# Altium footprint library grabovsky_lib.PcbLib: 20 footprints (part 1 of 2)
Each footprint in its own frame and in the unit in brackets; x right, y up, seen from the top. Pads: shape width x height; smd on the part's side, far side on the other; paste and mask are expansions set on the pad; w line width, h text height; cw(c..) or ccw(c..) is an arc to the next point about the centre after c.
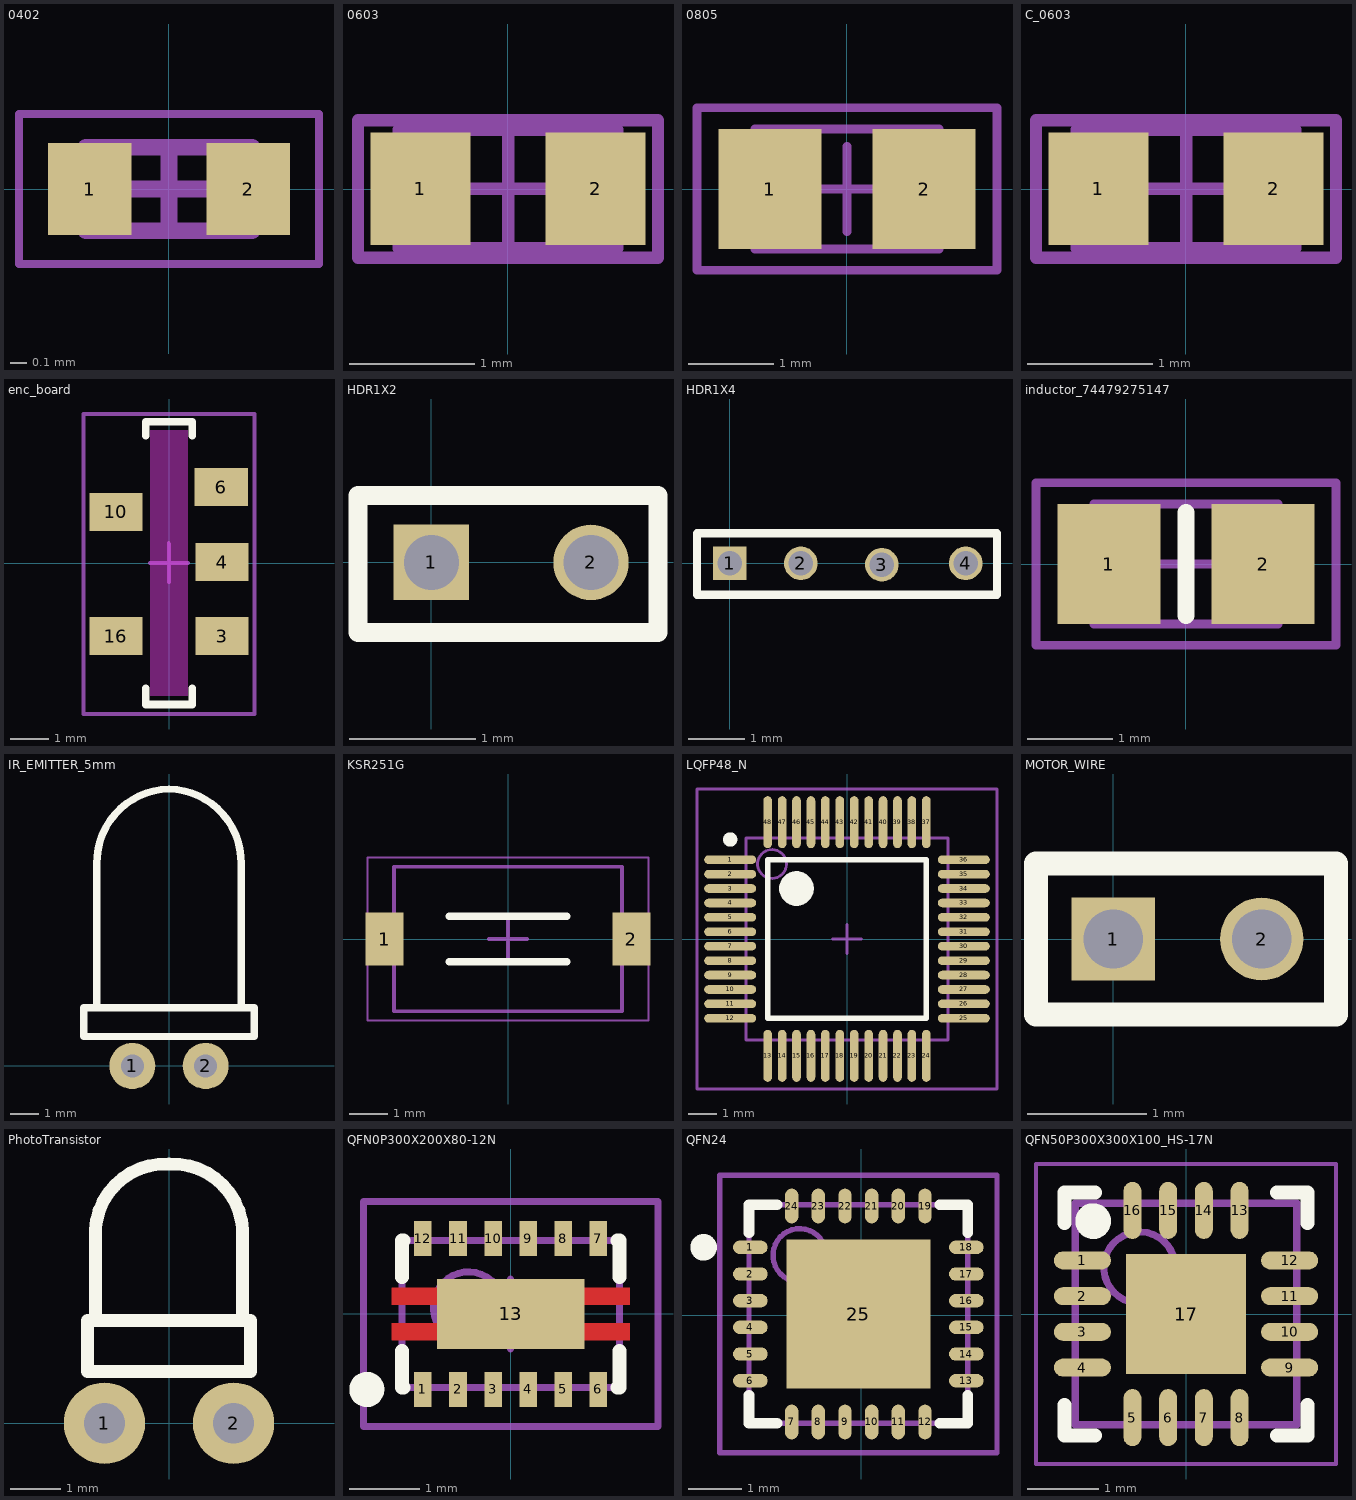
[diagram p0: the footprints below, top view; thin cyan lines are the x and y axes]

## 0402 [mm]
height 2
pads (2):
  rect 0.5x0.55 smd: 1(-0.475,0) 2(0.475,0)
Mechanical 13:
  lines w0.1: -0.5,-0.25 -0.5,0.25 0.5,0.25 0.5,-0.25 -0.5,-0.25
Mechanical 15:
  lines w0.05: -0.9,-0.45 -0.9,0.45 0.9,0.45 0.9,-0.45 -0.9,-0.45
  lines w0.1: -0.25,0 0.25,0 ; 0,-0.25 0,0.25
3D body "RES0402.stp": height 0.3, standoff 0, extent -0.5,-0.25 0.5,0.25

## 0603 [mm]
pads (2):
  rect 0.8x0.9 smd: 1(-0.7,0) 2(0.7,0)
Mechanical 13:
  lines w0.1: -0.875,-0.475 0.875,-0.475 0.875,0.475 -0.875,0.475 -0.875,-0.475
Mechanical 15:
  lines w0.1: -0.475,0 0.475,0 ; 0,-0.475 0,0.475 ; -1.2,-0.55 1.2,-0.55 1.2,0.55 -1.2,0.55 -1.2,-0.55
3D body "res0603r.STEP": height 0.45, standoff 0, extent -0.8,-0.4 0.8,0.4

## 0805 [mm]
pads (2):
  rect 1.2x1.4 smd: 1(-0.9,0) 2(0.9,0)
Mechanical 13:
  lines w0.1: -1.075,-0.7 -1.075,0.7 1.075,0.7 1.075,-0.7 -1.075,-0.7
Mechanical 15:
  lines w0.1: -0.5,0 0.5,0 ; 0,-0.5 0,0.5 ; -1.75,-0.95 -1.75,0.95 1.75,0.95 1.75,-0.95 -1.75,-0.95
3D body: height 0.7, standoff 0, extent -1.075,-0.7 1.075,0.7

## C_0603 [mm]
pads (2):
  rect 0.8x0.9 smd: 1(-0.7,0) 2(0.7,0)
Mechanical 13:
  lines w0.1: -0.875,-0.475 -0.875,0.475 0.875,0.475 0.875,-0.475 -0.875,-0.475
Mechanical 15:
  lines w0.1: -0.475,0 0.475,0 ; 0,-0.475 0,0.475 ; -1.2,-0.55 -1.2,0.55 1.2,0.55 1.2,-0.55 -1.2,-0.55
3D body "Ceramic CAP0603.stp": height 0.6, standoff 0, extent -0.8,-0.4 0.801,0.4

## enc_board [mm]
pads (5):
  rect 1.4x1 smd: 3(1.4,-1.925) 4(1.4,0.025) 6(1.375,2) 10(-1.4,1.35) 16(-1.4,-1.925)
Top Overlay:
  lines w0.2: -0.61,-3.302 -0.61,-3.726 0.61,-3.726 0.61,-3.302 ; -0.61,3.354 -0.61,3.726 0.61,3.726 0.61,3.354
Keep-Out Layer:
  board cut-out: -0.5,3.5 0.5,3.5 0.5,-3.5 -0.5,-3.5
Mechanical 15:
  lines w0.1: -0.5,0 0.5,0 ; -0.004,-0.474 -0.004,0.526 ; 0,-0.5 0,0.5 ; 2.25,-3.975 2.25,3.925 2.249,3.926 -2.249,3.926 -2.25,3.925 -2.25,-3.974 2.25,-3.974

## HDR1X2 [mm]
pads (2):
  rect 0.6x0.6 hole 0.44: 1(0,0)
  round 0.6 hole 0.44: 2(1.27,0)
Top Overlay:
  lines w0.15: -0.584,-0.559 1.803,-0.559 1.803,0.533 -0.584,0.533 -0.584,-0.559

## HDR1X4 [mm]
pads (4):
  rect 0.6x0.6 hole 0.44: 1(0,0)
  round 0.6 hole 0.44: 2(1.27,0) 3(2.718,-0.025) 4(4.216,0)
Top Overlay:
  lines w0.15: -0.584,-0.559 4.775,-0.559 4.775,0.533 -0.584,0.533 -0.584,-0.559

## inductor_74479275147 [mm]
pads (2):
  rect 1.2x1.4 smd: 1(-0.9,0) 2(0.9,0)
Top Overlay:
  lines w0.2: 0,-0.6 0,0.6
Mechanical 13:
  lines w0.1: -1.075,-0.7 -1.075,0.7 1.075,0.7 1.075,-0.7 -1.075,-0.7
Mechanical 15:
  lines w0.1: -0.5,0 0.5,0 ; 0,-0.5 0,0.5 ; -1.75,-0.95 -1.75,0.95 1.75,0.95 1.75,-0.95 -1.75,-0.95
3D body: height 0.7, standoff 0, extent -1.075,-0.7 1.075,0.7

## IR_EMITTER_5mm [mm]
pads (2):
  round 1.6 hole 0.8 mask+0.102: 1(-1.27,0) 2(1.27,0)
Top Overlay:
  lines w0.254: -2.5,2.02 -2.5,7 cw(c0.05,7.05) 0,9.6 cw(c-0.05,7.05) 2.5,7 2.5,2.02 ; -2.95,1.02 2.95,1.02 2.95,2.02 -2.95,2.02 -2.95,1.02
3D body "led5mm.STEP": height 10, standoff -2.24, extent -3,-0.25 2.5,9.55

## KSR251G [mm] "TACT SWITCH"
height 2.5
pads (2):
  rect 1x1.4 smd: 1(-3.25,0) 2(3.25,0)
Top Overlay:
  lines w0.2: -1.55,-0.6 1.55,-0.6 ; -1.55,0.6 1.55,0.6
Mechanical 13:
  lines w0.1: -3,-1.9 3,-1.9 3,1.9 -3,1.9 -3,-1.9
Mechanical 15:
  lines w0.05: -3.7,-2.15 3.7,-2.15 3.7,2.15 -3.7,2.15 -3.7,-2.15
  lines w0.1: -0.5,0 0.5,0 ; 0,-0.5 0,0.5
3D body: height 2.5, standoff 0, extent 2,-1.9 3,1.9
3D body: height 2.5, standoff 0, extent -3,-1.9 -2,1.9
3D body: height 2.5, standoff 0, extent -2,-1.9 2,1.9

## LQFP48_N [mm]
pads (48):
  oval 1.8x0.3 smd: 1(-4.05,2.75) 2(-4.05,2.25) 3(-4.05,1.75) 4(-4.05,1.25) 5(-4.05,0.75) 6(-4.05,0.25) 7(-4.05,-0.25) 8(-4.05,-0.75) 9(-4.05,-1.25) 10(-4.05,-1.75) 11(-4.05,-2.25) 12(-4.05,-2.75) 25(4.05,-2.75) 26(4.05,-2.25) 27(4.05,-1.75) 28(4.05,-1.25) 29(4.05,-0.75) 30(4.05,-0.25) 31(4.05,0.25) 32(4.05,0.75) 33(4.05,1.25) 34(4.05,1.75) 35(4.05,2.25) 36(4.05,2.75)
  oval 0.3x1.8 smd: 13(-2.75,-4.05) 14(-2.25,-4.05) 15(-1.75,-4.05) 16(-1.25,-4.05) 17(-0.75,-4.05) 18(-0.25,-4.05) 19(0.25,-4.05) 20(0.75,-4.05) 21(1.25,-4.05) 22(1.75,-4.05) 23(2.25,-4.05) 24(2.75,-4.05) 37(2.75,4.05) 38(2.25,4.05) 39(1.75,4.05) 40(1.25,4.05) 41(0.75,4.05) 42(0.25,4.05) 43(-0.25,4.05) 44(-0.75,4.05) 45(-1.25,4.05) 46(-1.75,4.05) 47(-2.25,4.05) 48(-2.75,4.05)
Top Overlay:
  circle w0.25: c-4.05,3.45 r0.125
  circle w0.6: c-1.75,1.75 r0.3
  lines w0.2: -2.75,-2.75 -2.75,2.75 2.75,2.75 2.75,-2.75 -2.75,-2.75
Mechanical 13:
  circle w0.1: c-2.6,2.6 r0.5
  lines w0.1: -3.5,-3.5 -3.5,3.5 3.5,3.5 3.5,-3.5 -3.5,-3.5
Mechanical 15:
  lines w0.1: -0.5,0 0.5,0 ; 0,-0.5 0,0.5 ; -5.2,-5.2 -5.2,5.2 5.2,5.2 5.2,-5.2 -5.2,-5.2
3D body: height 1.6, standoff 0, extent -3.5,-3.5 3.5,3.5

## MOTOR_WIRE [mm]
pads (2):
  rect 0.7x0.7 hole 0.5: 1(0,0)
  round 0.7 hole 0.5: 2(1.25,0)
Top Overlay:
  lines w0.2: -0.65,-0.635 1.875,-0.635 1.875,0.635 -0.65,0.635 -0.65,-0.635

## PhotoTransistor [mm]
pads (2):
  round 1.6 hole 0.8 mask+0.102: 1(-1.27,0) 2(1.27,0)
Top Overlay:
  lines w0.254: -1.45,2.02 -1.45,3.8 cw(c-0.075,3.725) 0,5.1 cw(c0.075,3.725) 1.45,3.8 1.45,2.02 ; -1.6,1.02 1.6,1.02 1.6,2.02 -1.6,2.02 -1.6,1.02
3D body "led3mm.STEP": height 3.45, standoff -3.3, extent -1.681,-0.15 1.65,5.35

## QFN0P300X200X80-12N [mm] "QFN, 12-Leads, Body 2,1x3,1mm (max), Pitch 0,50mm, Pitch1 0,00mm, IPC Medium Density"
height 0.8
pads (13):
  rect 0.25x0.5 smd: 1(-1.25,-1.075) 2(-0.75,-1.075) 3(-0.25,-1.075) 4(0.25,-1.075) 5(0.75,-1.075) 6(1.25,-1.075) 7(1.25,1.075) 8(0.75,1.075) 9(0.25,1.075) 10(-0.25,1.075) 11(-0.75,1.075) 12(-1.25,1.075)
  rect 2.1x1 smd: 13(0,0)
Top Layer:
  rectangle: -1.7,-0.375 -1,-0.125
  rectangle: -1.7,0.125 -1,0.375
  rectangle: 1,-0.375 1.7,-0.125
  rectangle: 1,0.125 1.7,0.375
Top Overlay:
  circle w0.25: c-2.05,-1.075 r0.125
  lines w0.2: -1.55,-0.525 -1.55,-1.05 -1.525,-1.05 ; -1.55,0.525 -1.55,1.05 -1.525,1.05 ; 1.525,-1.05 1.55,-1.05 1.55,-0.525 ; 1.525,1.05 1.55,1.05 1.55,0.525
Top Solder:
  rectangle: 1.143,-0.406 1.727,-0.102
  rectangle: 1.143,0.102 1.727,0.406
  rectangle: -1.727,-0.406 -1.143,-0.102
  rectangle: -1.73,0.1 -1.14,0.4
Mechanical 13:
  circle w0.1: c-0.6,0.1 r0.5
  lines w0.1: -1.55,-1.05 -1.55,1.05 1.55,1.05 1.55,-1.05 -1.55,-1.05
Mechanical 15:
  lines w0.1: -0.5,0 0.5,0 ; 0,-0.5 0,0.5 ; -2.1,-1.6 -2.1,1.6 2.1,1.6 2.1,-1.6 -2.1,-1.6
3D body: height 0.8, standoff 0, extent -1.55,-1.05 1.55,1.05

## QFN24 [mm]
pads (25):
  oval 0.65x0.25 smd: 1(-2.076,1.275) 2(-2.076,0.775) 3(-2.076,0.275) 4(-2.076,-0.225) 5(-2.076,-0.725) 6(-2.076,-1.225) 13(1.974,-1.225) 14(1.974,-0.725) 15(1.974,-0.225) 16(1.974,0.275) 17(1.974,0.775) 18(1.974,1.275)
  oval 0.25x0.65 smd: 7(-1.301,-2) 8(-0.801,-2) 9(-0.301,-2) 10(0.199,-2) 11(0.699,-2) 12(1.199,-2) 19(1.199,2.05) 20(0.699,2.05) 21(0.199,2.05) 22(-0.301,2.05) 23(-0.801,2.05) 24(-1.301,2.05)
  rect 2.7x2.8 smd: 25(-0.051,0.025)
Top Overlay:
  circle w0.25: c-2.951,1.275 r0.125
  lines w0.2: -2.101,-1.5 -2.101,-2.025 -1.576,-2.025 ; -2.101,1.55 -2.101,2.075 -1.576,2.075 ; 1.474,-2.025 1.999,-2.025 1.999,-1.5 ; 1.474,2.075 1.999,2.075 1.999,1.55
Mechanical 13:
  circle w0.1: c-1.151,1.125 r0.5
  lines w0.1: -2.101,-2.025 -2.101,2.075 1.999,2.075 1.999,-2.025 -2.101,-2.025
Mechanical 15:
  lines w0.1: -0.551,0.025 0.449,0.025 ; -0.051,-0.475 -0.051,0.525 ; -2.651,-2.575 -2.651,2.625 2.549,2.625 2.549,-2.575 -2.651,-2.575
3D body "User Library-QFN 24 4x4.step": height 0.9, standoff 0, extent -2.053,-1.981 1.951,2.023

## QFN50P300X300X100_HS-17N [mm]
pads (17):
  oval 0.8x0.25 smd: 1(-1.45,0.75) 2(-1.45,0.25) 3(-1.45,-0.25) 4(-1.45,-0.75) 9(1.45,-0.75) 10(1.45,-0.25) 11(1.45,0.25) 12(1.45,0.75)
  oval 0.25x0.8 smd: 5(-0.75,-1.45) 6(-0.25,-1.45) 7(0.25,-1.45) 8(0.75,-1.45) 13(0.75,1.45) 14(0.25,1.45) 15(-0.25,1.45) 16(-0.75,1.45)
  rect 1.68x1.68 smd: 17(0,0)
Top Overlay:
  circle w0.25: c-1.3,1.3 r0.125
  lines w0.2: -1.7,-1.275 -1.7,-1.7 -1.275,-1.7 ; -1.7,1.275 -1.7,1.7 -1.275,1.7 ; 1.275,-1.7 1.7,-1.7 1.7,-1.275 ; 1.275,1.7 1.7,1.7 1.7,1.275
Mechanical 13:
  circle w0.1: c-0.65,0.65 r0.5
  lines w0.1: -1.55,-1.55 1.55,-1.55 1.55,1.55 -1.55,1.55 -1.55,-1.55
Mechanical 15:
  lines w0.05: -2.1,-2.1 2.1,-2.1 2.1,2.1 -2.1,2.1 -2.1,-2.1
  lines w0.1: -0.5,0 0.5,0 ; 0,-0.5 0,0.5
3D body: height 1, standoff 0.05, extent -1.55,-1.55 1.55,1.55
